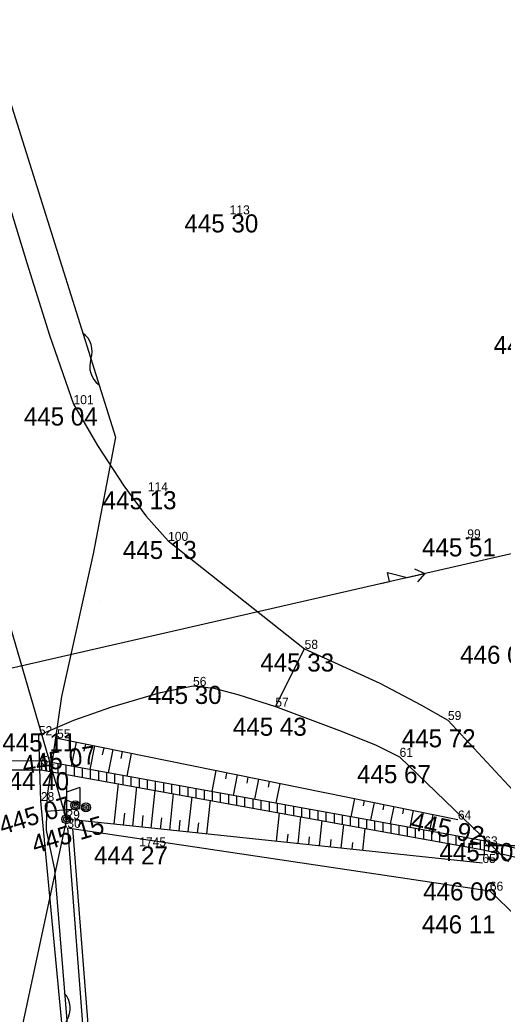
# Model space of a CAD drawing. Extents: x -559180 to -551373, y -1076947 to -1072071.
# Drawn here: x -553866.3 to -553839.6, y -1074543.7 to -1074488.6 of the extents above; entities that cross this region are included whole.
import ezdxf

# ---------------------------------------------------------------- set-up
doc = ezdxf.new("R2010")
doc.units = 0
for name, color, linetype in [('12_PLOTY', 7, 'Continuous'), ('13_PLOTY', 7, 'Continuous'), ('17_KOMUNIKACE', 7, 'Continuous'), ('18_POLOHOPIS', 7, 'Continuous'), ('1_VODA_ZN', 7, 'Continuous'), ('20_EL_ZN', 7, 'Continuous'), ('26_SRAFY', 7, 'Continuous'), ('27_HRANA_PATA', 7, 'Continuous'), ('28_VODA', 7, 'Continuous'), ('30_SDEL_ZN', 7, 'Continuous'), ('31_SDELOVACI', 7, 'Continuous'), ('32', 7, 'Continuous'), ('3_BODY', 7, 'Continuous'), ('40_KANAL_ZN', 7, 'Continuous'), ('6_VYSKY', 7, 'Continuous'), ('NNnadzemní', 7, 'Continuous')]:
    doc.layers.add(name, color=color, linetype=linetype)

# ---------------------------------------------------------------- blocks, each defined once
blk = doc.blocks.new('SLT')
at = {"layer": '30_SDEL_ZN'}
for radius in [0.25, 0.158, 0.05]:
    blk.add_circle((0, 0), radius, dxfattribs=at)
blk = doc.blocks.new('T')
at = {"layer": '6_VYSKY'}
blk.add_circle((0, 0), 0.05, dxfattribs=at)
blk = doc.blocks.new('VYUST')
at = {"layer": '40_KANAL_ZN'}
for p, q in [((-0.35, 0.5), (0, 0.5)), ((0, 0.5), (0, -0.5)), ((0, 0), (3, 0.001)), ((-0.35, -0.5), (0, -0.5))]:
    blk.add_line(p, q, dxfattribs=at)
blk = doc.blocks.new('ROZHLO')
at = {"layer": '30_SDEL_ZN'}
for p, q in [((0, 1.75), (0, 0)), ((0.75, 1.75), (0, 1.5)), ((0.75, 1.75), (0.75, 0.75)), ((0.75, 0.75), (0, 1.05))]:
    blk.add_line(p, q, dxfattribs=at)
blk = doc.blocks.new('SLB')
at = {"layer": '20_EL_ZN'}
for radius in [0.25, 0.158, 0.05]:
    blk.add_circle((0, 0), radius, dxfattribs=at)
blk = doc.blocks.new('POINT_DISPLAY')
blk.add_line((0, 0), (0, 0))
blk = doc.blocks.new('ELNN')
at = {"layer": '20_EL_ZN'}
for p, q in [((0, 0), (0.5, 0)), ((0.5, 0), (0.5, 0.5)), ((0.5, 0.5), (1.5, 0)), ((1.5, 0), (2.5, 0))]:
    blk.add_line(p, q, dxfattribs=at)
blk.add_lwpolyline([(2, 0.375), (2.5, 0), (2, -0.375)], dxfattribs=at)
blk = doc.blocks.new('SDEP')
at = {"layer": '30_SDEL_ZN'}
for centre, radius, start, end in [((0.75, -1.001), 1.251, 53.1529, 126.8469), ((2.25, 1), 1.25, 233.13, 306.8698)]:
    blk.add_arc(centre, radius, start, end, dxfattribs=at)

msp = doc.modelspace()

# ---------------------------------------------------------------- linework, layer by layer
at = {"layer": '12_PLOTY'}
for p, q in [((-553863.69, -1074533.37), (-553840.29, -1074536.85)), ((-553863.69, -1074533.37), (-553861.417, -1074562.635)), ((-553861.117, -1074562.612), (-553863.385, -1074533.415)), ((-553840.29, -1074536.85), (-553829.97, -1074546.91))]:
    msp.add_line(p, q, dxfattribs=at)
at = {"layer": '13_PLOTY'}
for p, q in [((-553869.46, -1074484.9), (-553861.02, -1074511.74)), ((-553861.02, -1074511.74), (-553862.26, -1074518.19)), ((-553862.26, -1074518.19), (-553864.01, -1074526.1)), ((-553864.01, -1074526.1), (-553864.8, -1074531.58)), ((-553864.8, -1074531.58), (-553864.844, -1074532.446)), ((-553864.844, -1074532.446), (-553864.86, -1074533.49)), ((-553864.86, -1074533.49), (-553864.4, -1074535.68)), ((-553864.4, -1074535.68), (-553863.4, -1074547.99))]:
    msp.add_line(p, q, dxfattribs=at)
at = {"layer": '17_KOMUNIKACE'}
for p, q in [((-553858.11, -1074517.48), (-553850.55, -1074523.46)), ((-553852.17, -1074526.66), (-553850.55, -1074523.46)), ((-553842.61, -1074527.4), (-553837.01, -1074533.45)), ((-553865.16, -1074531.89), (-553865.27, -1074528.24)), ((-553845.29, -1074529.44), (-553839.25, -1074535.26)), ((-553863.13, -1074553.38), (-553865.16, -1074531.89))]:
    msp.add_line(p, q, dxfattribs=at)
for points in [[(-553869.04, -1074491.97), (-553865.94, -1074502.084), (-553864.683, -1074506.086), (-553863.35, -1074509.91)], [(-553863.35, -1074509.91), (-553862.025, -1074512.205), (-553860.569, -1074514.435), (-553859.34, -1074516.093), (-553858.11, -1074517.48)], [(-553850.55, -1074523.46), (-553846.39, -1074525.361), (-553844.107, -1074526.554), (-553842.61, -1074527.4)], [(-553865.27, -1074528.24), (-553863.34, -1074527.415), (-553861.226, -1074526.672), (-553858.54, -1074525.871), (-553856.73, -1074525.51)], [(-553856.73, -1074525.51), (-553855.569, -1074525.642), (-553854.255, -1074525.986), (-553852.17, -1074526.66)], [(-553852.17, -1074526.66), (-553848.475, -1074528.044), (-553846.589, -1074528.789), (-553845.29, -1074529.44)]]:
    msp.add_lwpolyline(points, dxfattribs=at)
at = {"layer": '18_POLOHOPIS'}
msp.add_line((-553864.844, -1074532.446), (-553862.982, -1074532.307), dxfattribs=at)
at = {"layer": '26_SRAFY'}
for p, q in [((-553863.452, -1074529.949), (-553863.185, -1074528.628)), ((-553862.755, -1074529.124), (-553862.675, -1074528.731)), ((-553862.429, -1074530.134), (-553862.166, -1074528.835)), ((-553861.735, -1074529.324), (-553861.656, -1074528.938)), ((-553861.406, -1074530.319), (-553861.147, -1074529.041)), ((-553860.715, -1074529.524), (-553860.638, -1074529.144)), ((-553860.383, -1074530.504), (-553860.128, -1074529.248)), ((-553855.677, -1074531.356), (-553855.442, -1074530.197)), ((-553854.921, -1074530.661), (-553854.852, -1074530.317)), ((-553854.491, -1074531.571), (-553854.261, -1074530.437)), ((-553853.739, -1074530.893), (-553853.671, -1074530.557)), ((-553853.305, -1074531.785), (-553853.08, -1074530.676)), ((-553852.556, -1074531.125), (-553852.49, -1074530.796)), ((-553860.875, -1074530.924), (-553861.112, -1074533.167)), ((-553859.857, -1074531.108), (-553860.086, -1074533.275)), ((-553858.839, -1074531.293), (-553859.06, -1074533.384)), ((-553852.119, -1074532), (-553851.899, -1074530.916)), ((-553857.821, -1074531.477), (-553858.034, -1074533.492)), ((-553856.803, -1074531.661), (-553857.008, -1074533.6)), ((-553855.785, -1074531.845), (-553855.982, -1074533.708)), ((-553847.966, -1074532.752), (-553847.764, -1074531.754)), ((-553847.282, -1074532.16), (-553847.222, -1074531.864)), ((-553846.878, -1074532.949), (-553846.68, -1074531.974)), ((-553846.196, -1074532.373), (-553846.138, -1074532.083)), ((-553845.789, -1074533.146), (-553845.596, -1074532.193)), ((-553845.111, -1074532.586), (-553845.054, -1074532.303)), ((-553844.7, -1074533.343), (-553844.511, -1074532.413)), ((-553860.529, -1074532.56), (-553860.599, -1074533.221)), ((-553859.505, -1074532.691), (-553859.573, -1074533.33)), ((-553858.482, -1074532.822), (-553858.547, -1074533.438)), ((-553857.458, -1074532.953), (-553857.521, -1074533.546)), ((-553851.964, -1074532.537), (-553852.13, -1074534.114)), ((-553850.775, -1074532.752), (-553850.932, -1074534.241)), ((-553849.586, -1074532.967), (-553849.734, -1074534.367)), ((-553844.025, -1074532.799), (-553843.969, -1074532.523)), ((-553843.611, -1074533.54), (-553843.427, -1074532.633)), ((-553856.435, -1074533.084), (-553856.495, -1074533.654)), ((-553848.397, -1074533.183), (-553848.536, -1074534.494)), ((-553847.208, -1074533.398), (-553847.337, -1074534.62)), ((-553851.483, -1074533.718), (-553851.531, -1074534.178)), ((-553850.287, -1074533.871), (-553850.333, -1074534.304)), ((-553849.092, -1074534.024), (-553849.135, -1074534.43)), ((-553847.896, -1074534.177), (-553847.936, -1074534.557))]:
    msp.add_line(p, q, dxfattribs=at)
at = {"layer": '27_HRANA_PATA'}
for p, q in [((-553864.26, -1074528.41), (-553842.06, -1074532.91)), ((-553840.7, -1074535.32), (-553863.74, -1074532.89))]:
    msp.add_line(p, q, dxfattribs=at)
at = {"layer": '28_VODA'}
for p, q in [((-553869.845, -1074529.659), (-553865.102, -1074529.65)), ((-553865.102, -1074529.65), (-553840.44, -1074534.114)), ((-553869.794, -1074530.158), (-553865.157, -1074530.149)), ((-553865.157, -1074530.149), (-553840.645, -1074534.586)), ((-553840.44, -1074534.114), (-553835.463, -1074535.29)), ((-553840.645, -1074534.586), (-553839.626, -1074534.826)), ((-553834.882, -1074535.982), (-553839.626, -1074534.826))]:
    msp.add_line(p, q, dxfattribs=at)
at = {"layer": '31_SDELOVACI'}
for q in [(-553870.335, -1074510.284), (-553870.202, -1074562.934)]:
    msp.add_line((-553863.74, -1074532.89), q, dxfattribs=at)
at = {"layer": '32'}
for p, q in [((-553865.102, -1074530.159), (-553865.102, -1074529.65)), ((-553864.652, -1074530.242), (-553864.652, -1074529.731)), ((-553864.202, -1074530.324), (-553864.202, -1074529.813)), ((-553863.752, -1074530.406), (-553863.752, -1074529.894)), ((-553863.302, -1074530.489), (-553863.302, -1074529.976)), ((-553862.852, -1074530.571), (-553862.852, -1074530.057)), ((-553862.402, -1074530.654), (-553862.402, -1074530.139)), ((-553861.952, -1074530.729), (-553861.952, -1074530.22)), ((-553861.502, -1074530.811), (-553861.502, -1074530.302)), ((-553861.052, -1074530.892), (-553861.052, -1074530.383)), ((-553860.602, -1074530.974), (-553860.602, -1074530.465)), ((-553860.152, -1074531.055), (-553860.152, -1074530.546)), ((-553859.702, -1074531.136), (-553859.702, -1074530.627)), ((-553859.252, -1074531.218), (-553859.252, -1074530.709)), ((-553858.802, -1074531.299), (-553858.802, -1074530.79)), ((-553858.352, -1074531.381), (-553858.352, -1074530.872)), ((-553857.902, -1074531.462), (-553857.902, -1074530.953)), ((-553857.452, -1074531.544), (-553857.452, -1074531.035)), ((-553857.002, -1074531.625), (-553857.002, -1074531.116)), ((-553856.552, -1074531.707), (-553856.552, -1074531.198)), ((-553856.102, -1074531.788), (-553856.102, -1074531.279)), ((-553855.652, -1074531.87), (-553855.652, -1074531.361)), ((-553855.202, -1074531.951), (-553855.202, -1074531.442)), ((-553854.752, -1074532.032), (-553854.752, -1074531.523)), ((-553854.302, -1074532.114), (-553854.302, -1074531.605)), ((-553853.852, -1074532.195), (-553853.852, -1074531.686)), ((-553853.402, -1074532.277), (-553853.402, -1074531.768)), ((-553852.952, -1074532.358), (-553852.952, -1074531.849)), ((-553852.502, -1074532.44), (-553852.502, -1074531.931)), ((-553852.052, -1074532.521), (-553852.052, -1074532.012)), ((-553851.602, -1074532.603), (-553851.602, -1074532.094)), ((-553851.152, -1074532.684), (-553851.152, -1074532.175)), ((-553850.702, -1074532.766), (-553850.702, -1074532.257)), ((-553850.252, -1074532.847), (-553850.252, -1074532.338)), ((-553849.802, -1074532.928), (-553849.802, -1074532.419)), ((-553849.352, -1074533.01), (-553849.352, -1074532.501)), ((-553848.902, -1074533.091), (-553848.902, -1074532.582)), ((-553848.452, -1074533.173), (-553848.452, -1074532.664)), ((-553848.002, -1074533.254), (-553848.002, -1074532.745)), ((-553847.552, -1074533.336), (-553847.552, -1074532.827)), ((-553847.102, -1074533.417), (-553847.102, -1074532.908)), ((-553846.652, -1074533.499), (-553846.652, -1074532.99)), ((-553846.202, -1074533.58), (-553846.202, -1074533.071)), ((-553845.752, -1074533.662), (-553845.752, -1074533.152)), ((-553845.302, -1074533.743), (-553845.302, -1074533.234)), ((-553844.852, -1074533.824), (-553844.852, -1074533.315)), ((-553844.402, -1074533.906), (-553844.402, -1074533.397)), ((-553843.952, -1074533.987), (-553843.952, -1074533.478)), ((-553843.502, -1074534.069), (-553843.502, -1074533.56)), ((-553843.052, -1074534.15), (-553843.052, -1074533.641)), ((-553842.602, -1074534.232), (-553842.602, -1074533.723)), ((-553842.152, -1074534.313), (-553842.152, -1074533.804)), ((-553841.702, -1074534.395), (-553841.702, -1074533.886)), ((-553841.252, -1074534.476), (-553841.252, -1074533.967)), ((-553840.802, -1074534.558), (-553840.802, -1074534.048)), ((-553840.352, -1074534.655), (-553840.352, -1074534.135)), ((-553839.902, -1074534.761), (-553839.902, -1074534.241))]:
    msp.add_line(p, q, dxfattribs=at)
at = {"layer": 'NNnadzemní'}
msp.add_line((-553869.639, -1074525.168), (-553834.15, -1074517.05), dxfattribs=at)

# ---------------------------------------------------------------- block references
at = {"layer": '1_VODA_ZN'}
for p in [(-553854.7, -1074499.4), (-553863.35, -1074509.91), (-553859.23, -1074514.73), (-553858.11, -1074517.48), (-553841.54, -1074517.34), (-553861.873, -1074520.854), (-553861.873, -1074520.854), (-553861.87, -1074520.85), (-553850.55, -1074523.46), (-553856.73, -1074525.51), (-553852.17, -1074526.66), (-553842.61, -1074527.4), (-553865.27, -1074528.24), (-553864.26, -1074528.41), (-553845.29, -1074529.44), (-553865.13, -1074529.9), (-553865.16, -1074531.89), (-553863.74, -1074532.89), (-553842.06, -1074532.91), (-553863.69, -1074533.37), (-553859.71, -1074534.4), (-553840.6, -1074534.34), (-553840.7, -1074535.32), (-553840.29, -1074536.85)]:
    msp.add_blockref('POINT_DISPLAY', p, dxfattribs=at)
at = {"layer": '20_EL_ZN', "xscale": 1.0000002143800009, "yscale": 1.0000002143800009, "rotation": 12.88452853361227}
msp.add_blockref('ELNN', (-553846.33, -1074519.836), dxfattribs=at)
at = {"layer": '20_EL_ZN', "rotation": 90}
for p in [(-553863.25, -1074532.117), (-553862.665, -1074532.241)]:
    msp.add_blockref('SLB', p, dxfattribs=at)
at = {"layer": '30_SDEL_ZN'}
for p, xscale, yscale, rotation in [((-553862.833, -1074505.973), 0.9999989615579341, 0.9999989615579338, -72.54388847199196), ((-553863.843, -1074542.536), 1.0000004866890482, 1.0000004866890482, -85.35571769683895)]:
    msp.add_blockref('SDEP', p, dxfattribs=dict(at, xscale=xscale, yscale=yscale, rotation=rotation))
for name in ['ROZHLO', 'SLT']:
    msp.add_blockref(name, (-553863.74, -1074532.89), dxfattribs=at)
at = {"layer": '40_KANAL_ZN'}
msp.add_blockref('VYUST', (-553840.6, -1074534.34), dxfattribs=at)
at = {"layer": '6_VYSKY'}
msp.add_blockref('T', (-553841.54, -1074517.34), dxfattribs=at)
msp.add_blockref('T', (-553841.54, -1074517.34), dxfattribs=at)

# ---------------------------------------------------------------- texts
at = {"layer": '3_BODY'}
for s, p in [('113', (-553854.7, -1074499.4)), ('101', (-553863.35, -1074509.91)), ('114', (-553859.23, -1074514.73)), ('100', (-553858.11, -1074517.48)), ('99', (-553841.54, -1074517.34)), ('58', (-553850.55, -1074523.46)), ('56', (-553856.73, -1074525.51)), ('57', (-553852.17, -1074526.66)), ('59', (-553842.61, -1074527.4)), ('52', (-553865.27, -1074528.24)), ('55', (-553864.26, -1074528.41)), ('61', (-553845.29, -1074529.44)), ('51', (-553865.13, -1074529.9)), ('28', (-553865.16, -1074531.89)), ('29', (-553863.74, -1074532.89)), ('64', (-553842.06, -1074532.91)), ('30', (-553863.69, -1074533.37)), ('1745', (-553859.71, -1074534.4)), ('63', (-553840.6, -1074534.34)), ('65', (-553840.7, -1074535.32)), ('66', (-553840.29, -1074536.85))]:
    msp.add_text(s, height=0.5, dxfattribs=at).set_placement(p)
at = {"layer": '6_VYSKY'}
for s, p in [('445 30', (-553857.205, -1074500.4)), ('446 92', (-553840.075, -1074507.13)), ('445 04', (-553866.1, -1074511.094)), ('445 13', (-553861.735, -1074515.73)), ('445 13', (-553860.615, -1074518.48)), ('445 51', (-553844.045, -1074518.34)), ('446 07', (-553841.933, -1074524.286)), ('445 33', (-553853.004, -1074524.715)), ('445 30', (-553859.235, -1074526.51)), ('445 43', (-553854.522, -1074528.272)), ('445 72', (-553845.166, -1074528.91)), ('445 11', (-553867.291, -1074529.138)), ('444 40', (-553867.686, -1074531.283)), ('445 67', (-553847.643, -1074530.899)), ('444 27', (-553862.215, -1074535.4)), ('444 27', (-553862.215, -1074535.4)), ('444 27', (-553862.215, -1074535.4)), ('445 30', (-553843.079, -1074535.212)), ('446 06', (-553843.981, -1074537.39)), ('446 11', (-553844.056, -1074539.214))]:
    msp.add_text(s, height=1, dxfattribs=at).set_placement(p)
for s, rotation, p in [('445 07', 8.3296, (-553866.107, -1074530.39)), ('445 07', 17.2171, (-553867.291, -1074533.755)), ('445 15', 16.5541, (-553865.482, -1074534.8)), ('445 92', 347.4712, (-553844.733, -1074533.448))]:
    msp.add_text(s, height=1, rotation=rotation, dxfattribs=at).set_placement(p)

doc.saveas('drawing.dxf')
